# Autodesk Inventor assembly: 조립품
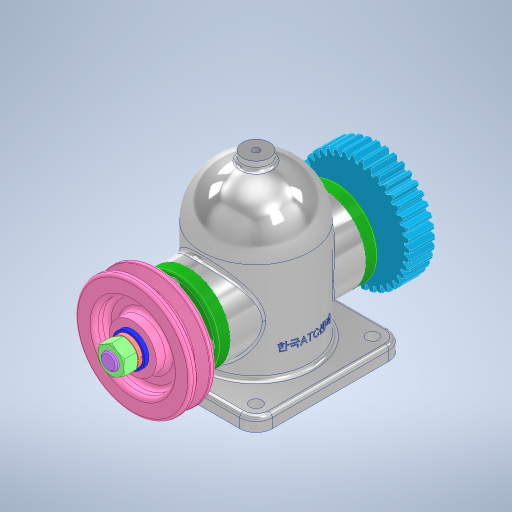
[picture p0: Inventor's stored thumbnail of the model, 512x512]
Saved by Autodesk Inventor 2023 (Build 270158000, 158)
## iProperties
Created: 2025-04
Part Number: 조립품
Document SubType Name: Assembly
Designer: ADMIN_PC
Author: ADMIN_PC
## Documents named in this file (14)
- C:\Users\ADMIN_PC\Desktop\750406V1007\조립품.iam
- C:\Users\ADMIN_PC\Desktop\750406V1007\본체.ipt
- C:\Users\ADMIN_PC\Desktop\750406V1007\깊은 홈 볼 베어링 6203.ipt
- C:\Users\ADMIN_PC\Desktop\750406V1007\축.ipt
- C:\Users\ADMIN_PC\Desktop\750406V1007\커버.ipt
- C:\Users\ADMIN_PC\Desktop\750406V1007\오일 실 26 38 8.ipt
- C:\Users\ADMIN_PC\Desktop\750406V1007\6각 구멍붙이 볼트 M4x12.ipt
- C:\Users\ADMIN_PC\Desktop\750406V1007\칼라.ipt
- C:\Users\ADMIN_PC\Desktop\750406V1007\평행 키 5x5x12.ipt
- C:\Users\ADMIN_PC\Desktop\750406V1007\스퍼기어.ipt
- C:\Users\ADMIN_PC\Desktop\750406V1007\V 벨트 풀리.ipt
- C:\Users\ADMIN_PC\Desktop\750406V1007\평와셔 M12.ipt
- C:\Users\ADMIN_PC\Desktop\750406V1007\스프링 와셔 M12.ipt
- C:\Users\ADMIN_PC\Desktop\750406V1007\6각 너트 M12x1.ipt
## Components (11 placed, 3 different names)
1. 6각 구멍붙이 볼트 M4x12:1
2. 6각 구멍붙이 볼트 M4x12:2
3. 6각 구멍붙이 볼트 M4x12:3
4. 6각 구멍붙이 볼트 M4x12:4
5. 6각 구멍붙이 볼트 M4x12:5
6. 6각 구멍붙이 볼트 M4x12:6
7. 6각 구멍붙이 볼트 M4x12:7
8. 6각 구멍붙이 볼트 M4x12:8
9. V 벨트 풀리:1
10. 6각 너트 M12x1:1
11. 6각 너트 M12x1:2
